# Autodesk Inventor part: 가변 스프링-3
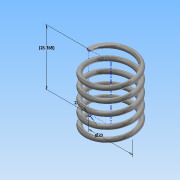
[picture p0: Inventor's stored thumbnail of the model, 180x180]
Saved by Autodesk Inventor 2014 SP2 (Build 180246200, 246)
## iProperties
Created: 2016-01
Part Number: 가변 스프링-3
Material: 스테인레스 스틸
Document SubType Name: Modeling
Designer: Administrator
Density: 8.08 g/cm^3
Appearance: 반연마
Mass: 7.84117 g
Surface Area: 19.6953 cm^2
Volume: 0.970441 cm^3
Author: Administrator
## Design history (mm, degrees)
sketch "스케치2"
  geometry: L1 (0, 0)-(10, 0); L2 (10, 0)-(10, 25.358); L3 (10, 25.358)-(0, 25.358); L4 (0, 25.358)-(0, 0); C1 r 1 at (10, 0)
  constraints: 8 end point, 2 parallel, 1 centre point, 1 coincident, 1 horizontal, 1 perpendicular
  dimensions: "d0" = 2 diameter of C1; "d1" = 20 diameter of L2 L4; "d2" = 25.35829 distance between parallel lines of L3 L1 (derived)
feature "코일1" pitch "d3" = 10; turns "d5" = 5; dims "d4" = 25.35829 (= d2), "d6" = 0, angle "d7" = 90 deg, angle "d8" = 90 deg, "d9" = 0, "d10" = 0
sketch "스케치3"
  geometry: L1 (-11, 0)-(-9, 0) reference; 1 further point
  constraints: 1 horizontal alignment
extrude "돌출1" cut sketch "스케치3" stored distance "d11" = 10; taper "d12" = 0 deg
node "작업 평면1"
sketch "스케치4"
  geometry: L1 (1, 0)-(-1, 0) reference; 1 further point
  constraints: 1 horizontal alignment
extrude "돌출2" cut sketch "스케치4" stored distance "d14" = 10; taper "d15" = 0 deg
node "솔리드1"
node "절단 모서리 투영1"
node "절단 모서리 투영2"
other parameters: "d13" = 0
